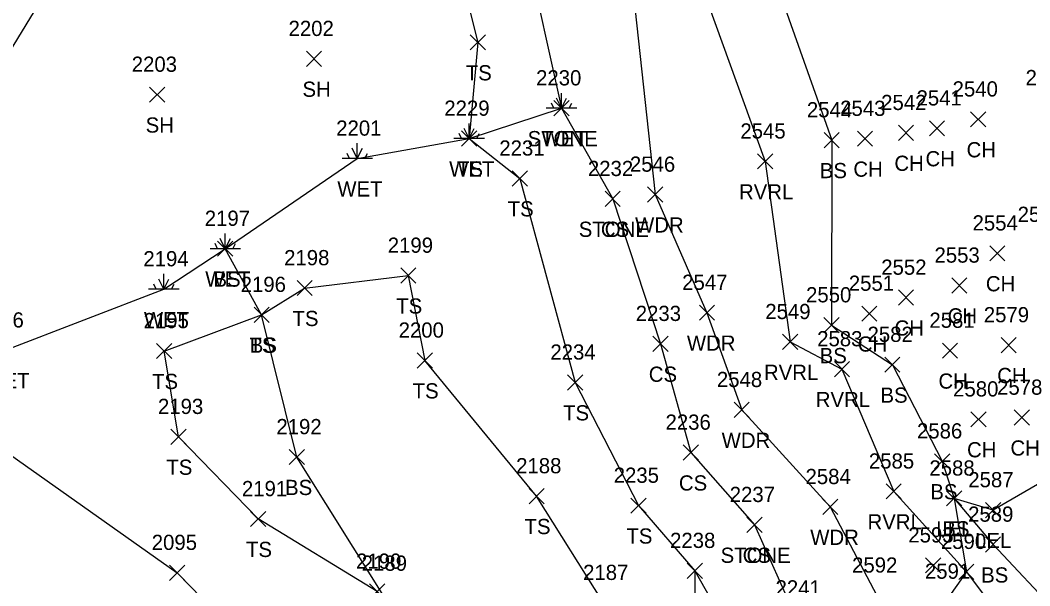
# Model space of a CAD drawing. Extents: x 1512665 to 1513714, y 110636 to 112816.
# Drawn here: x 1512914.5 to 1513047.2, y 110908.3 to 110982.6 of the extents above; entities that cross this region are included whole.
import ezdxf

# ---------------------------------------------------------------- set-up
doc = ezdxf.new("R2010")
doc.units = 0
for name, color, linetype in [('L_A', 7, 'Continuous'), ('L_I', 7, 'Continuous'), ('L_TIC', 7, 'Continuous'), ('LARO', 7, 'Continuous'), ('LASF', 7, 'Continuous'), ('LAWA', 7, 'Continuous'), ('LAWE', 7, 'Continuous'), ('LELB', 7, 'Continuous'), ('LWET', 7, 'Continuous')]:
    doc.layers.add(name, color=color, linetype=linetype)

msp = doc.modelspace()

# ---------------------------------------------------------------- linework, layer by layer
at = {"layer": 'L_TIC'}
for points in [[(1512973.66, 110978.72), (1512975.66, 110980.72)], [(1512975.66, 110978.72), (1512973.66, 110980.72)], [(1512952.12, 110976.56), (1512954.12, 110978.56)], [(1512954.12, 110976.56), (1512952.12, 110978.56)], [(1512931.51, 110971.85), (1512933.51, 110973.85)], [(1512933.51, 110971.85), (1512931.51, 110973.85)], [(1512984.65, 110970.06), (1512986.65, 110972.06)], [(1512986.65, 110970.06), (1512984.65, 110972.06)], [(1513039.4, 110968.6), (1513041.4, 110970.6)], [(1513041.4, 110968.6), (1513039.4, 110970.6)], [(1513029.92, 110966.82), (1513031.92, 110968.82)], [(1513031.92, 110966.82), (1513029.92, 110968.82)], [(1513034, 110967.42), (1513036, 110969.42)], [(1513036, 110967.42), (1513034, 110969.42)], [(1512972.51, 110966.07), (1512974.51, 110968.07)], [(1512974.51, 110966.07), (1512972.51, 110968.07)], [(1513020.16, 110965.86), (1513022.16, 110967.86)], [(1513022.16, 110965.86), (1513020.16, 110967.86)], [(1513024.53, 110966.05), (1513026.53, 110968.05)], [(1513026.53, 110966.05), (1513024.53, 110968.05)], [(1513011.42, 110963.07), (1513013.42, 110965.07)], [(1513013.42, 110963.07), (1513011.42, 110965.07)], [(1512979.17, 110960.83), (1512981.17, 110962.83)], [(1512981.17, 110960.83), (1512979.17, 110962.83)], [(1512991.38, 110958.14), (1512993.38, 110960.14)], [(1512993.38, 110958.14), (1512991.38, 110960.14)], [(1512991.38, 110958.14), (1512993.38, 110960.14)], [(1512993.38, 110958.14), (1512991.38, 110960.14)], [(1512996.96, 110958.71), (1512998.96, 110960.71)], [(1512998.96, 110958.71), (1512996.96, 110960.71)], [(1512940.46, 110951.59), (1512942.46, 110953.59)], [(1512942.46, 110951.59), (1512940.46, 110953.59)], [(1513041.93, 110950.98), (1513043.93, 110952.98)], [(1513043.93, 110950.98), (1513041.93, 110952.98)], [(1512964.52, 110948.05), (1512966.52, 110950.05)], [(1512966.52, 110948.05), (1512964.52, 110950.05)], [(1512950.89, 110946.41), (1512952.89, 110948.41)], [(1512952.89, 110946.41), (1512950.89, 110948.41)], [(1513036.93, 110946.75), (1513038.93, 110948.75)], [(1513038.93, 110946.75), (1513036.93, 110948.75)], [(1513029.93, 110945.16), (1513031.93, 110947.16)], [(1513031.93, 110945.16), (1513029.93, 110947.16)], [(1513003.77, 110943.17), (1513005.77, 110945.17)], [(1513005.77, 110943.17), (1513003.77, 110945.17)], [(1513025.1, 110943.05), (1513027.1, 110945.05)], [(1513027.1, 110943.05), (1513025.1, 110945.05)], [(1512945.24, 110942.9), (1512947.24, 110944.9)], [(1512947.24, 110942.9), (1512945.24, 110944.9)], [(1512945.24, 110942.9), (1512947.24, 110944.9)], [(1512947.24, 110942.9), (1512945.24, 110944.9)], [(1513020.14, 110941.53), (1513022.14, 110943.53)], [(1513022.14, 110941.53), (1513020.14, 110943.53)], [(1512997.67, 110939.08), (1512999.67, 110941.08)], [(1512999.67, 110939.08), (1512997.67, 110941.08)], [(1513014.69, 110939.33), (1513016.69, 110941.33)], [(1513016.69, 110939.33), (1513014.69, 110941.33)], [(1512932.43, 110938.13), (1512934.43, 110940.13)], [(1512934.43, 110938.13), (1512932.43, 110940.13)], [(1513035.7, 110938.18), (1513037.7, 110940.18)], [(1513037.7, 110938.18), (1513035.7, 110940.18)], [(1513043.42, 110938.91), (1513045.42, 110940.91)], [(1513045.42, 110938.91), (1513043.42, 110940.91)], [(1512966.68, 110936.89), (1512968.68, 110938.89)], [(1512968.68, 110936.89), (1512966.68, 110938.89)], [(1512966.68, 110936.89), (1512968.68, 110938.89)], [(1512968.68, 110936.89), (1512966.68, 110938.89)], [(1513028.13, 110936.33), (1513030.13, 110938.33)], [(1513030.13, 110936.33), (1513028.13, 110938.33)], [(1513021.51, 110935.75), (1513023.51, 110937.75)], [(1513023.51, 110935.75), (1513021.51, 110937.75)], [(1512986.45, 110934), (1512988.45, 110936)], [(1512988.45, 110934), (1512986.45, 110936)], [(1513008.33, 110930.39), (1513010.33, 110932.39)], [(1513010.33, 110930.39), (1513008.33, 110932.39)], [(1513039.46, 110929.15), (1513041.46, 110931.15)], [(1513041.46, 110929.15), (1513039.46, 110931.15)], [(1513045.16, 110929.38), (1513047.16, 110931.38)], [(1513047.16, 110929.38), (1513045.16, 110931.38)], [(1512934.31, 110926.85), (1512936.31, 110928.85)], [(1512936.31, 110926.85), (1512934.31, 110928.85)], [(1513001.64, 110924.78), (1513003.64, 110926.78)], [(1513003.64, 110924.78), (1513001.64, 110926.78)], [(1512949.88, 110924.19), (1512951.88, 110926.19)], [(1512951.88, 110924.19), (1512949.88, 110926.19)], [(1513034.68, 110923.63), (1513036.68, 110925.63)], [(1513036.68, 110923.63), (1513034.68, 110925.63)], [(1512981.38, 110919.05), (1512983.38, 110921.05)], [(1512983.38, 110919.05), (1512981.38, 110921.05)], [(1513028.31, 110919.67), (1513030.31, 110921.67)], [(1513030.31, 110919.67), (1513028.31, 110921.67)], [(1512994.77, 110917.8), (1512996.77, 110919.8)], [(1512996.77, 110917.8), (1512994.77, 110919.8)], [(1513036.26, 110918.75), (1513038.26, 110920.75)], [(1513038.26, 110918.75), (1513036.26, 110920.75)], [(1513036.26, 110918.75), (1513038.26, 110920.75)], [(1513038.26, 110918.75), (1513036.26, 110920.75)], [(1513019.98, 110917.63), (1513021.98, 110919.63)], [(1513021.98, 110917.63), (1513019.98, 110919.63)], [(1513041.37, 110917.21), (1513043.37, 110919.21)], [(1513043.37, 110917.21), (1513041.37, 110919.21)], [(1512944.78, 110916.04), (1512946.78, 110918.04)], [(1512946.78, 110916.04), (1512944.78, 110918.04)], [(1513010.02, 110915.27), (1513012.02, 110917.27)], [(1513012.02, 110915.27), (1513010.02, 110917.27)], [(1513010.02, 110915.27), (1513012.02, 110917.27)], [(1513012.02, 110915.27), (1513010.02, 110917.27)], [(1513041.36, 110912.68), (1513043.36, 110914.68)], [(1513043.36, 110912.68), (1513041.36, 110914.68)], [(1513033.49, 110909.95), (1513035.49, 110911.95)], [(1513035.49, 110909.95), (1513033.49, 110911.95)], [(1512934.14, 110908.97), (1512936.14, 110910.97)], [(1512936.14, 110908.97), (1512934.14, 110910.97)], [(1513002.18, 110909.23), (1513004.18, 110911.23)], [(1513004.18, 110909.23), (1513002.18, 110911.23)], [(1513002.18, 110909.23), (1513004.18, 110911.23)], [(1513004.18, 110909.23), (1513002.18, 110911.23)], [(1513037.86, 110909.1), (1513039.86, 110911.1)], [(1513039.86, 110909.1), (1513037.86, 110911.1)], [(1513037.86, 110909.1), (1513039.86, 110911.1)], [(1513039.86, 110909.1), (1513037.86, 110911.1)], [(1512960.43, 110906.5), (1512962.43, 110908.5)], [(1512962.43, 110906.5), (1512960.43, 110908.5)]]:
    msp.add_lwpolyline(points, dxfattribs=at)
at = {"layer": 'LARO'}
msp.add_lwpolyline([(1513054.78, 110925.92), (1513051.54, 110923.52), (1513042.37, 110918.21), (1513037.26, 110919.75), (1513038.86, 110910.1), (1513036.11, 110906.18), (1513030.6, 110898.71), (1513032.35, 110888.01), (1513034.03, 110875.07), (1513033.74, 110859.16), (1513040, 110853.34), (1513041.84, 110847.28), (1513041.35, 110841.63), (1513042.36, 110832.47), (1513042.54, 110822.43), (1513049.44, 110822.77)], dxfattribs=at)
at = {"layer": 'LASF'}
for points in [[(1512966.2, 111086.67), (1512969.13, 111066.32), (1512971.94, 111045.46), (1512980.86, 111021.96), (1512978.76, 111015.54), (1512980.96, 110992.24), (1512985.65, 110971.06), (1512992.38, 110959.14)], [(1513011.02, 110916.27), (1513016.47, 110903.98), (1513018.79, 110891.62), (1513019.5, 110879.02), (1513015.58, 110859.28), (1513021.8, 110848.84), (1513037.12, 110847.47)]]:
    msp.add_lwpolyline(points, dxfattribs=at)
at = {"layer": 'LAWA'}
msp.add_lwpolyline([(1512977.18, 111087.04), (1512979.22, 111069.38), (1512984.42, 111047.27), (1512989.63, 111015.62), (1512994.85, 110988.4), (1512997.96, 110959.71), (1513004.77, 110944.17), (1513009.33, 110931.39), (1513020.98, 110918.63), (1513027.1, 110906.99), (1513030.6, 110898.71), (1513042.86, 110889.73), (1513042.54, 110875.66), (1513037.08, 110875.12), (1513033.74, 110859.16), (1513040, 110853.34)], dxfattribs=at)
at = {"layer": 'LAWE'}
msp.add_lwpolyline([(1512987.72, 111088.08), (1512984.9, 111070.15), (1512990.77, 111049.14), (1512998.03, 111015.44), (1513003.05, 110990.02), (1513012.42, 110964.07), (1513015.69, 110940.33), (1513022.51, 110936.75), (1513029.31, 110920.67), (1513038.86, 110910.1), (1513045.15, 110901.71)], dxfattribs=at)
at = {"layer": 'LELB'}
for points in [[(1512999.92, 111089.04), (1513004.14, 111053.62), (1513005.26, 111016.8), (1513012.57, 110991.14), (1513021.16, 110966.86), (1513021.14, 110942.53), (1513029.13, 110937.33), (1513035.68, 110924.63), (1513037.26, 110919.75), (1513042.36, 110913.68), (1513051.02, 110904.49)], [(1512881, 111069.89), (1512889.28, 111054.32), (1512904.05, 111034.19), (1512918.02, 111009.83), (1512920.13, 110990.07), (1512909.26, 110972.23), (1512893.57, 110955.66)], [(1512980.86, 111021.96), (1512966.16, 111016.97), (1512966.08, 111012.92), (1512971.64, 110991.75), (1512974.66, 110979.72), (1512973.51, 110967.07), (1512980.17, 110961.83), (1512987.45, 110935), (1512995.77, 110918.8), (1513003.18, 110910.23), (1513008.97, 110899.99), (1513018.79, 110891.62), (1513028.51, 110881.74), (1513026.69, 110865.34), (1513034.96, 110851.42)], [(1512992.38, 110959.14), (1512998.67, 110940.08), (1513002.64, 110925.78), (1513011.02, 110916.27)], [(1512974.87, 110808.35), (1512980.8, 110812.11), (1512984.12, 110822.65), (1512983.37, 110849.35), (1512977.75, 110867.95), (1512974, 110889.11), (1512962.1, 110907.23), (1512950.88, 110925.19), (1512946.24, 110943.9), (1512941.46, 110952.59)], [(1512974.87, 110808.35), (1512979.1, 110813.19), (1512980.27, 110823.71), (1512983.37, 110849.35), (1512972.28, 110865.98), (1512966.82, 110886.58), (1512961.43, 110907.5), (1512945.78, 110917.04), (1512935.31, 110927.85), (1512933.43, 110939.13), (1512946.24, 110943.9), (1512951.89, 110947.41), (1512965.52, 110949.05), (1512967.68, 110937.89)], [(1512874.79, 110940.29), (1512901.47, 110933.01), (1512911.25, 110926.84), (1512935.14, 110909.97), (1512951.52, 110893.13), (1512955.62, 110874.23), (1512953.44, 110855.33)], [(1512988.2, 110800.66), (1512991.09, 110811.8), (1512992.54, 110824.89), (1512993.99, 110850.15), (1512990.9, 110870.01), (1512992.23, 110882.23), (1512991.18, 110906.02), (1512982.38, 110920.05), (1512967.68, 110937.89)], [(1513003.18, 110910.23), (1513003.22, 110897.09), (1513008.12, 110876.95), (1513004.02, 110858.75), (1513009.43, 110844.58), (1513003.95, 110835.59)]]:
    msp.add_lwpolyline(points, dxfattribs=at)
at = {"layer": 'LWET'}
for p, q in [((1512985.65, 110971.06), (1512985.65, 110973.06)), ((1512984.65, 110971.06), (1512984.32, 110971.73)), ((1512985.65, 110971.06), (1512984.99, 110972.4)), ((1512985.65, 110971.06), (1512986.32, 110972.4)), ((1512986.65, 110971.06), (1512986.99, 110971.73)), ((1512987.65, 110971.06), (1512983.65, 110971.06)), ((1512973.51, 110967.07), (1512973.51, 110969.07)), ((1512972.51, 110967.07), (1512972.18, 110967.74)), ((1512973.51, 110967.07), (1512972.85, 110968.4)), ((1512973.51, 110967.07), (1512974.18, 110968.4)), ((1512974.51, 110967.07), (1512974.85, 110967.74)), ((1512958.81, 110964.45), (1512958.81, 110966.45)), ((1512975.51, 110967.07), (1512971.51, 110967.07)), ((1512957.81, 110964.45), (1512957.48, 110965.12)), ((1512958.81, 110964.45), (1512958.15, 110965.79)), ((1512958.81, 110964.45), (1512959.48, 110965.79)), ((1512959.81, 110964.45), (1512960.15, 110965.12)), ((1512960.81, 110964.45), (1512956.81, 110964.45)), ((1512941.46, 110952.59), (1512941.46, 110954.59)), ((1512940.46, 110952.59), (1512940.13, 110953.25)), ((1512941.46, 110952.59), (1512940.8, 110953.92)), ((1512941.46, 110952.59), (1512942.13, 110953.92)), ((1512942.46, 110952.59), (1512942.8, 110953.25)), ((1512943.46, 110952.59), (1512939.46, 110952.59)), ((1512933.39, 110947.27), (1512933.39, 110949.27)), ((1512932.39, 110947.27), (1512932.06, 110947.94)), ((1512933.39, 110947.27), (1512932.73, 110948.6)), ((1512933.39, 110947.27), (1512934.06, 110948.6)), ((1512934.39, 110947.27), (1512934.73, 110947.94)), ((1512935.39, 110947.27), (1512931.39, 110947.27))]:
    msp.add_line(p, q, dxfattribs=at)
msp.add_lwpolyline([(1512828.68, 110967.97), (1512826.31, 110951.24), (1512831.67, 110950.26), (1512846.81, 110959.22), (1512852.71, 110961.86), (1512857.83, 110959.55), (1512867.09, 110954.96), (1512874.74, 110954.61), (1512893.57, 110955.66), (1512912.43, 110939.22), (1512933.39, 110947.27), (1512941.46, 110952.59), (1512958.81, 110964.45), (1512973.51, 110967.07), (1512985.65, 110971.06)], dxfattribs=at)

# ---------------------------------------------------------------- texts
at = {"layer": 'L_A'}
for s, p in [('TS', (1512973.07, 110974.72)), ('SH', (1512951.61, 110972.56)), ('SH', (1512931, 110967.85)), ('STONE', (1512981.2, 110966.06)), ('WET', (1512983.03, 110966.06)), ('CH', (1513038.89, 110964.6)), ('CH', (1513029.4, 110962.82)), ('CH', (1513033.49, 110963.42)), ('WET', (1512970.89, 110962.07)), ('TS', (1512971.92, 110962.07)), ('BS', (1513019.6, 110961.86)), ('CH', (1513024.01, 110962.05)), ('WET', (1512956.19, 110959.45)), ('RVRL', (1513008.98, 110959.07)), ('TS', (1512978.58, 110956.83)), ('STONE', (1512987.92, 110954.14)), ('CS', (1512990.82, 110954.14)), ('WDR', (1512995.32, 110954.71)), ('WET', (1512938.84, 110947.59)), ('BS', (1512939.91, 110947.59)), ('CH', (1513041.42, 110946.98)), ('TS', (1512963.93, 110944.05)), ('WET', (1512930.77, 110942.27)), ('TS', (1512950.3, 110942.41)), ('CH', (1513036.41, 110942.75)), ('CH', (1513029.42, 110941.16)), ('WDR', (1513002.13, 110939.17)), ('CH', (1513024.59, 110939.05)), ('TS', (1512944.65, 110938.9)), ('BS', (1512944.68, 110938.9)), ('BS', (1513019.58, 110937.53)), ('CS', (1512997.12, 110935.08)), ('RVRL', (1513012.26, 110935.33)), ('WET', (1512909.81, 110934.22)), ('TS', (1512931.84, 110934.13)), ('CH', (1513035.19, 110934.18)), ('CH', (1513042.91, 110934.91)), ('TS', (1512966.09, 110932.89)), ('TS', (1512966.09, 110932.89)), ('BS', (1513027.57, 110932.33)), ('RVRL', (1513019.07, 110931.75)), ('TS', (1512985.86, 110930)), ('WDR', (1513006.7, 110926.39)), ('CH', (1513038.95, 110925.15)), ('CH', (1513044.65, 110925.38)), ('TS', (1512933.72, 110922.85)), ('CS', (1513001.08, 110920.78)), ('BS', (1512949.32, 110920.19)), ('BS', (1513034.12, 110919.63)), ('TS', (1512980.79, 110915.05)), ('RVRL', (1513025.87, 110915.67)), ('TS', (1512994.18, 110913.8)), ('LEL', (1513034.9, 110914.75)), ('BS', (1513035.7, 110914.75)), ('WDR', (1513018.34, 110913.63)), ('LEL', (1513040.01, 110913.21)), ('TS', (1512944.19, 110912.04)), ('STONE', (1513006.56, 110911.27)), ('CS', (1513009.46, 110911.27)), ('BS', (1513040.8, 110908.68))]:
    msp.add_text(s, height=2, dxfattribs=at).set_placement(p)
at = {"layer": 'L_I'}
for s, p in [('2202', (1512949.78, 110980.56)), ('2203', (1512929.17, 110975.85)), ('2230', (1512982.31, 110974.06)), ('2230', (1512982.31, 110974.06)), ('2539', (1513046.64, 110974.09)), ('2540', (1513037.05, 110972.6)), ('2542', (1513027.66, 110970.82)), ('2541', (1513032.31, 110971.42)), ('2229', (1512970.25, 110970.07)), ('2229', (1512970.25, 110970.07)), ('2544', (1513017.9, 110969.86)), ('2543', (1513022.27, 110970.05)), ('2201', (1512956.04, 110967.45)), ('2545', (1513009.16, 110967.07)), ('2231', (1512977.48, 110964.83)), ('2232', (1512989.12, 110962.14)), ('2232', (1512989.12, 110962.14)), ('2546', (1512994.64, 110962.71)), ('2197', (1512938.77, 110955.59)), ('2197', (1512938.77, 110955.59)), ('2554', (1513039.67, 110954.98)), ('2555', (1513045.6, 110956.11)), ('2199', (1512962.82, 110952.05)), ('2194', (1512930.7, 110950.27)), ('2198', (1512949.2, 110950.41)), ('2553', (1513034.67, 110950.75)), ('2552', (1513027.67, 110949.16)), ('2196', (1512943.49, 110946.9)), ('2196', (1512943.49, 110946.9)), ('2547', (1513001.51, 110947.17)), ('2551', (1513023.41, 110947.05)), ('2550', (1513017.79, 110945.53)), ('2233', (1512995.41, 110943.08)), ('2549', (1513012.43, 110943.33)), ('2579', (1513041.15, 110942.91)), ('2086', (1512909.04, 110942.22)), ('2195', (1512930.73, 110942.13)), ('2581', (1513034, 110942.18)), ('2200', (1512964.25, 110940.89)), ('2200', (1512964.25, 110940.89)), ('2582', (1513025.87, 110940.33)), ('2583', (1513019.25, 110939.75)), ('2234', (1512984.19, 110938)), ('2548', (1513006.07, 110934.39)), ('2580', (1513037.12, 110933.15)), ('2578', (1513042.9, 110933.38)), ('2193', (1512932.62, 110930.85)), ('2236', (1512999.32, 110928.78)), ('2192', (1512948.18, 110928.19)), ('2586', (1513032.37, 110927.63)), ('2188', (1512979.69, 110923.05)), ('2585', (1513026.05, 110923.67)), ('2235', (1512992.51, 110921.8)), ('2588', (1513034, 110922.75)), ('2588', (1513034, 110922.75)), ('2584', (1513017.72, 110921.63)), ('2587', (1513039.11, 110921.21)), ('2191', (1512943.65, 110920.04)), ('2237', (1513007.76, 110919.27)), ('2237', (1513007.76, 110919.27)), ('2589', (1513039.09, 110916.68)), ('2593', (1513031.23, 110913.95)), ('2095', (1512931.8, 110912.97)), ('2238', (1512999.92, 110913.23)), ('2238', (1512999.92, 110913.23)), ('2590', (1513035.51, 110913.1)), ('2590', (1513035.51, 110913.1)), ('2190', (1512958.65, 110910.5)), ('2189', (1512959.4, 110910.23)), ('2592', (1513023.84, 110909.99)), ('2187', (1512988.49, 110909.02)), ('2591', (1513033.41, 110909.18)), ('2591', (1513033.41, 110909.18)), ('2241', (1513013.78, 110906.98))]:
    msp.add_text(s, height=2, dxfattribs=at).set_placement(p)

doc.saveas('drawing.dxf')
